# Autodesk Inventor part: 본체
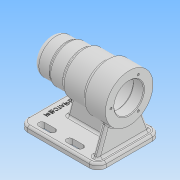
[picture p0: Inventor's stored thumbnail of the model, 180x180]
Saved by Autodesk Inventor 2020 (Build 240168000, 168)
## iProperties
Created: 2021-10
Part Number: 본체
Material: 일반
Document SubType Name: Modeling
Designer: user
Density: 1 g/cm^3
Appearance: 기본값
Author: user
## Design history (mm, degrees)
sketch "스케치1"
  geometry: L1 (56, 0)-(-56, 0); L2 (-56, 0)-(-56, 25); L3 (-56, 25)-(-32, 25); L4 (-32, 25)-(-32, 27); L5 (-32, 27)-(-10, 27); L6 (-10, 27)-(-10, 30); L7 (-10, 30)-(24, 30); L8 (24, 30)-(24, 34); L9 (24, 34)-(56, 34); L10 (56, 34)-(56, 0); 1 further point
  constraints: 20 end point, 7 perpendicular, 1 horizontal, 1 vertical
  dimensions: "d0" = 112 distance of L1.start L1.end; "d1" = 25 distance of L1.end L2.end; "d2" = 24 distance of L2.end L3.end; "d3" = 2 distance of L3.end L4.end; "d5" = 3 distance of L5.end L6.end; "d6" = 34 distance of L6.end L7.end; "d7" = 4 distance of L7.end L8.end; "d8" = 32 distance of L8.end L9.end; "d9" = 56 distance from line of point (0, 0) L2; "d10" = 34 distance from line of point (0, 0) L9; "d89" = 46 distance between parallel lines of L2 L6
revolve "회전1" sketch "스케치1" stored, may be unused: angle "d11" = 90 deg
node "작업 평면1"
sketch "스케치2"
  geometry: L1 (56, -45)-(-56, -45); L2 (-56, -45)-(-56, 45); L3 (-56, 45)-(56, 45); L4 (56, 45)-(56, -45); L5 (56, -45)-(-56, 45); L6 (-56, -45)-(56, 45); 1 further point
  constraints: 12 end point, 2 midpoint, 2 parallel, 1 horizontal, 1 perpendicular
  dimensions: "d13" = 112 distance of L1.start L1.end; "d14" = 90 distance of L1.end L2.end
extrude "돌출1" join sketch "스케치2" distance "d15" = 8; taper "d16" = 0 deg
sketch "스케치3"
  geometry: L1 (48, -4)-(-29, -4); L2 (-29, -4)-(-29, 4); L3 (-29, 4)-(48, 4); L4 (48, 4)-(48, -4); L5 (48, -4)-(-29, 4); L6 (-29, -4)-(48, 4); L7 (56, -45)-(56, 45) reference; 2 further points
  constraints: 12 end point, 2 midpoint, 2 parallel, 1 horizontal, 1 perpendicular
  dimensions: "d18" = 77 distance of L2.end L3.end; "d19" = 8 distance of L1.end L2.end; "d20" = 8 distance between parallel lines of L7 L4; "d21" = 4 distance from line of point (0, 0) L3
extrude "돌출2" join sketch "스케치3" stored distance "d22" = 8; taper "d23" = 0 deg
sketch "스케치4"
  geometry: L1 (-45, -62)-(45, -62) reference; L2 (-23.409, -24.658)-(-37, -62); L3 (23.409, -24.658)-(37, -62); L4 (-4, -62)-(-4, -33.764) reference; L5 (4, -62)-(4, -33.764) reference; L6 (-45, -70)-(-45, -62) reference; L7 (-45, -62)-(-4, -62) reference; L8 (-4, -62)-(-4, -33.764) reference; L9 (4, -33.764)-(4, -62) reference; L10 (4, -62)-(45, -62) reference; L11 (45, -62)-(45, -70) reference; L12 (45, -70)-(-45, -70) reference; L13 (-4, -62)-(4, -62) reference; A1 r 34 centre (0, 0) between (-23.409, -24.658) and (23.409, -24.658) reference; A2 r 34 centre (0, 0) between (4, -33.764) and (-4, -33.764) reference; A3 r 34 centre (0, 0) between (-4, -33.764) and (4, -33.764) reference
  constraints: 4 end point, 2 point on circle, 2 point on line
  dimensions: "d24" = 110 deg angle of L1 L2; "d25" = 8 distance of L2.end L1.start; "d26" = 110 deg angle of L1 L3; "d27" = 8 distance of L1.end L3.end
extrude "돌출3" join sketch "스케치4" distance "d28" = 8; taper "d29" = 0 deg
sketch "스케치5"
  geometry: C1 r 34 at (0, 0) reference; C2 r 21 at (0, 0)
  constraints: 1 centre point, 1 coincident
  dimensions: "d31" = 42 diameter of C2
feature "면 기울기1" dims angle "d30" = 15 deg
extrude "돌출4" cut sketch "스케치5" distance "d32" = 15; taper "d33" = 0 deg
sketch "스케치6"
  geometry: C1 r 21 at (0, 0) reference; C2 r 24 at (0, 0)
  constraints: 1 centre point, 1 coincident
  dimensions: "d34" = 48 diameter of C2
extrude "돌출5" cut sketch "스케치6" distance "d35" = 54; taper "d36" = 0 deg
sketch "스케치7"
  geometry: C1 r 24 at (0, 0) reference; C2 r 21 at (0, 0)
  constraints: 1 centre point, 1 coincident
  dimensions: "d37" = 42 diameter of C2
extrude "돌출6" cut sketch "스케치7" distance "d38" = 12; taper "d39" = 0 deg
sketch "스케치8"
  geometry: C1 r 21 at (0, 0) reference; C2 r 17.5 at (0, 0)
  constraints: 1 centre point, 1 coincident
  dimensions: "d40" = 35 diameter of C2
extrude "돌출7" cut sketch "스케치8" distance "d41" = 18; taper "d42" = 0 deg
sketch "스케치9"
  geometry: C1 r 17.5 at (0, 0) reference; C2 r 16 at (0, 0)
  constraints: 1 centre point, 1 coincident
  dimensions: "d43" = 32 diameter of C2
extrude "돌출8" cut sketch "스케치9" distance "d44" = 4; taper "d45" = 0 deg
sketch "스케치10"
  geometry: C1 r 16 at (0, 0) reference; C2 r 10.5 at (0, 0)
  constraints: 1 centre point, 1 coincident
  dimensions: "d46" = 21 diameter of C2
extrude "돌출9" cut sketch "스케치10" distance "d47" = 3; taper "d48" = 0 deg
sketch "스케치11" dims "d49" = 52
  geometry: C1 r 21 at (0, 0) reference; C2 r 34 at (0, 0) reference; 2 further points
  constraints: 2 horizontal alignment, 1 coincident, 2 other
hole "구멍1" sketch "스케치11" at (-26, 0) diameter "d50" = 3.242; stored, may be unused: countersink angle "d54" = 90 deg, drill point angle "d56" = 118 deg; dims "d51" = 8, "d52" = 4, "d53" = 2, "d55" = 11
sketch "스케치12"
  geometry: L1 (-56, 45)-(-56, -45) reference; L2 (56, 45)-(-56, 45) reference; L3 (40, -4)-(-29, -4) reference; L4 (-36, 33)-(-21, 33); L5 (-36, 28.5)-(-21, 28.5); L6 (-21, 37.5)-(-36, 37.5); L7 (4, 28.5)-(19, 28.5); L8 (4, 33)-(19, 33); L9 (19, 37.5)-(4, 37.5); A1 r 4.5 centre (-36, 33) between (-36, 37.5) and (-36, 28.5); A2 r 4.5 centre (-21, 33) between (-21, 28.5) and (-21, 37.5); A3 r 4.5 centre (19, 33) between (19, 28.5) and (19, 37.5); A4 r 4.5 centre (4, 33) between (4, 37.5) and (4, 28.5); 3 further points
  constraints: 16 end point, 8 point on circle, 8 tangent, 4 centre point, 3 parallel, 2 midpoint
  dimensions: "d60" = 15 distance of L4.start L4.end; "d61" = 20 distance from line of L1 L4.start; "d63" = 9 distance between parallel lines of L5 L6; "d64" = 33 vertical distance of point (0, 0) L4.start; "d65" = 15 distance of L8.start L8.end; "d66" = 9 distance between parallel lines of L7 L9; "d67" = 25 distance of L4.end L8.start; "d68" = 33 vertical distance of point (0, 0) L8.start; "d69" = 12 distance from line of L2 L8.end
extrude "돌출10" cut sketch "스케치12" extent not by distance; stored distance "d70" = 71.367; taper "d71" = 0 deg
fillet "모깎기1" dims "d72" = 12
fillet "모깎기2" dims "d73" = 3
fillet "모깎기3" dims "d74" = 3
fillet "모깎기4" dims "d75" = 3
fillet "모깎기5" dims "d76" = 8
chamfer "모따기1" distance "d78" = 1; stored, may be unused: second distance "d79" = 2, angle "d80" = 45 deg
sketch "스케치13"
  geometry: L1 (-56, 33)-(-56, -33) reference; 2 further points
  constraints: 1 horizontal alignment, 1 other
  dimensions: "d81" = 12 distance from line of L1 point (-44, 0)
fillet "모깎기7" dims "d82" = 3
fillet "모깎기8" dims "d83" = 3
fillet "모깎기9" dims "d84" = 3
feature "엠보싱1" dims "d0" = 112, "d1" = 25, "d2" = 24, "d3" = 2, "d5" = 3, "d6" = 34, "d7" = 4, "d8" = 32, "d9" = 56, "d10" = 34, "d85" = 0.5, "d86" = 0, "d89" = 46
fillet "모깎기10" dims "d87" = 0.3
fillet "모깎기11" dims "d88" = 3
node "솔리드1"
pattern_circular "원형 패턴1" dims angle "d58" = 360 deg
mirror "미러1"
node "절단 모서리 투영1"
feature "A9D066F2-1C7D-4E18-AEED-F7BC21143FA4" dims "d50" = 3.242, "d51" = 8, "d52" = 4, "d53" = 2, "d54" = 90 deg, "d55" = 11, "d56" = 118 deg
